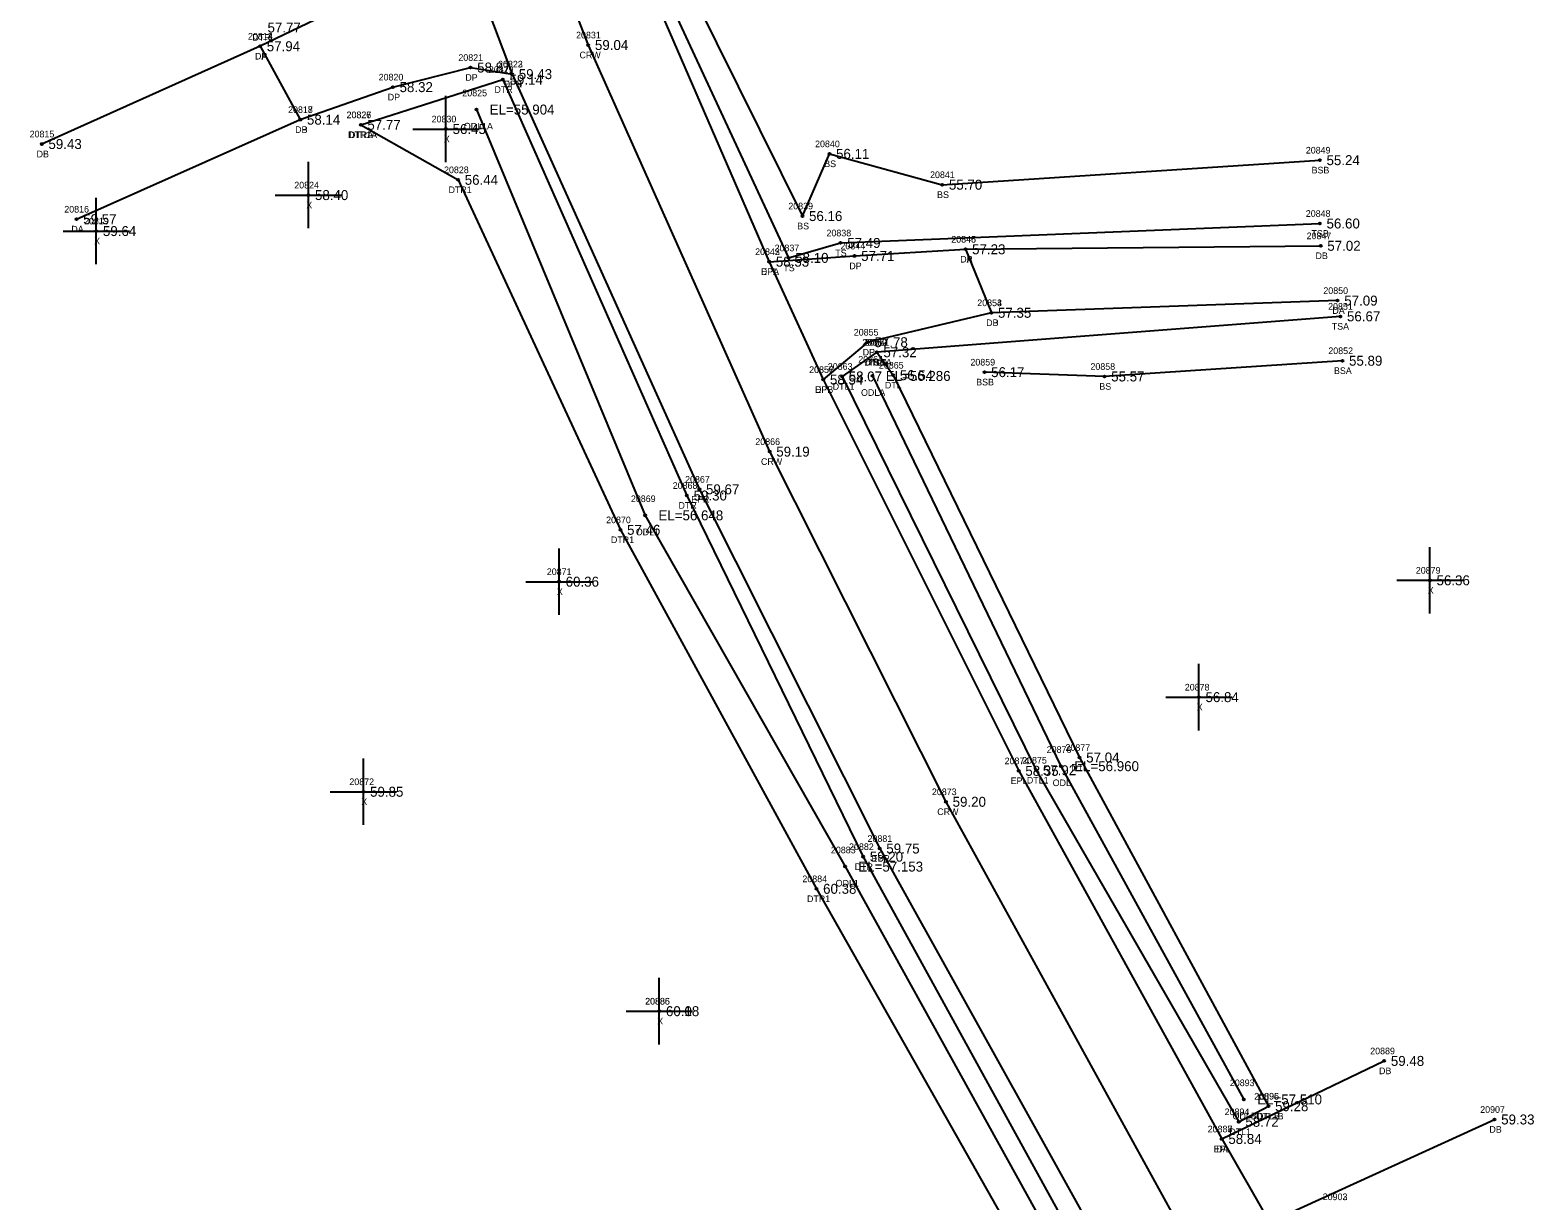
# Model space of a CAD drawing. Extents: x 2396547 to 2397655, y 770185 to 772649.
# Drawn here: x 2397059 to 2397285.6, y 770939.8 to 771116.1 of the extents above; entities that cross this region are included whole.
import ezdxf

# ---------------------------------------------------------------- set-up
doc = ezdxf.new("R2010")
doc.units = 0
for name, color, linetype in [('RD_DTM_BkLn1', 7, 'Continuous'), ('RD_DTM_BkLn2', 7, 'Continuous'), ('RD_DTM_BkLn_txCode', 7, 'Continuous'), ('RD_EX_Driveway', 7, 'Continuous'), ('RD_EX_Driveway_txCode', 7, 'Continuous'), ('RD_EX_H2O', 7, 'Continuous'), ('RD_EX_H2O_txCode', 7, 'Continuous'), ('RD_EX_Misc', 7, 'Continuous'), ('RD_EX_Misc_txCode', 7, 'Continuous'), ('RD_EX_Road', 7, 'Continuous'), ('RD_EX_Road_txCode', 7, 'Continuous'), ('RD_EX_TX_Driveway_ELEV', 7, 'Continuous'), ('RD_EX_TX_H2O_ELEV', 7, 'Continuous'), ('RD_EX_TX_Misc_ELEV', 7, 'Continuous'), ('RD_EX_TX_Road_ELEV', 7, 'Continuous'), ('RD_HC_Survey_ELEV', 7, 'Continuous'), ('RD_HC_Survey_txCode', 7, 'Continuous'), ('RD_SMD_Locator', 7, 'Continuous')]:
    doc.layers.add(name, color=color, linetype=linetype)

msp = doc.modelspace()

# ---------------------------------------------------------------- linework, layer by layer
at = {"layer": 'RD_DTM_BkLn1'}
msp.add_lwpolyline([(2397104.78, 771217.07), (2397119.02, 771175.87), (2397143.13, 771113.88), (2397170.45, 771052.64), (2397197.01, 770999.9), (2397235.12, 770930.63), (2397270.14, 770871.5)], dxfattribs=at)
at = {"layer": 'RD_DTM_BkLn2'}
msp.add_line((2397256.41, 771073.01), (2397186.58, 771067.61), dxfattribs=at)
for points in [[(2397076.78, 771367.04), (2397097.18, 771355.59), (2397095.19, 771340.51), (2397107.46, 771294.95), (2397125.86, 771232.19), (2397125.86, 771232.19), (2397138.17, 771181.02), (2397159.24, 771120.76), (2397175.38, 771088.12), (2397179.45, 771097.49), (2397196.45, 771092.84), (2397253.33, 771096.54)], [(2397076.87, 771363.73), (2397092.63, 771353.52), (2397090.96, 771344.27), (2397084.99, 771338.48), (2397096.6, 771290.87), (2397116.69, 771229.78), (2397116.69, 771229.78), (2397133.23, 771179.22), (2397155.87, 771119.34), (2397173.3, 771081.82), (2397181.13, 771084.07), (2397253.33, 771087)], [(2397256.72, 771066.33), (2397220.89, 771063.96), (2397202.81, 771064.61)]]:
    msp.add_lwpolyline(points, dxfattribs=at)
at = {"layer": 'RD_EX_Driveway'}
for p, q in [((2397093.7, 771113.7), (2397060.81, 771098.97)), ((2397066.05, 771087.65), (2397099.75, 771102.64)), ((2397199.94, 771083.12), (2397253.45, 771083.64)), ((2397256, 771075.39), (2397203.84, 771073.55)), ((2397238.54, 770949.11), (2397263.02, 770960.87)), ((2397245.72, 770936.59), (2397279.64, 770952.05))]:
    msp.add_line(p, q, dxfattribs=at)
for points in [[(2397122.66, 771133.29), (2397116.06, 771126.12), (2397107.96, 771120.55), (2397093.7, 771113.7), (2397099.75, 771102.64), (2397113.7, 771107.54), (2397125.39, 771110.49), (2397131.66, 771109.5)], [(2397170.38, 771081.25), (2397183.23, 771082.11), (2397199.94, 771083.12), (2397203.84, 771073.55), (2397185.24, 771069.12), (2397178.53, 771063.49)]]:
    msp.add_lwpolyline(points, dxfattribs=at)
at = {"layer": 'RD_EX_H2O'}
for points in [[(2397108.85, 771101.86), (2397130.27, 771108.67), (2397157.99, 771046.03), (2397184.53, 770991.63), (2397224.53, 770918.86), (2397257.48, 770863.23)], [(2397126.28, 771104.16), (2397151.7, 771043.04), (2397181.8, 770990.14), (2397222.13, 770917.32), (2397255.11, 770861.71)], [(2397108.85, 771101.86), (2397123.52, 771093.58), (2397147.97, 771040.86), (2397177.5, 770986.79), (2397217.86, 770915.5), (2397251.15, 770859.33)], [(2397186.58, 771067.61), (2397181.36, 771063.96), (2397210.6, 771004.65), (2397241.1, 770951.7), (2397245.58, 770954.05)], [(2397186.58, 771067.61), (2397189.06, 771064.15), (2397217.13, 771006.57), (2397245.58, 770954.05)], [(2397185.94, 771064.04), (2397214.32, 771005.26), (2397241.89, 770955.07)]]:
    msp.add_lwpolyline(points, dxfattribs=at)
at = {"layer": 'RD_EX_Misc'}
for p, q in [((2397121.69, 771096.23), (2397121.69, 771106.23)), ((2397116.69, 771101.23), (2397126.69, 771101.23)), ((2397100.96, 771086.28), (2397100.96, 771096.28)), ((2397069.02, 771080.86), (2397069.02, 771090.86)), ((2397095.96, 771091.28), (2397105.96, 771091.28)), ((2397064.02, 771085.86), (2397074.02, 771085.86)), ((2397138.72, 771028.05), (2397138.72, 771038.05)), ((2397269.9, 771028.26), (2397269.9, 771038.26)), ((2397264.9, 771033.26), (2397274.9, 771033.26)), ((2397133.72, 771033.05), (2397143.72, 771033.05)), ((2397235.1, 771010.66), (2397235.1, 771020.66)), ((2397230.1, 771015.66), (2397240.1, 771015.66)), ((2397109.26, 770996.41), (2397109.26, 771006.41)), ((2397104.26, 771001.41), (2397114.26, 771001.41)), ((2397153.83, 770963.36), (2397153.83, 770973.36)), ((2397153.83, 770963.36), (2397153.83, 770973.36)), ((2397148.83, 770968.36), (2397158.83, 770968.36)), ((2397148.83, 770968.36), (2397158.83, 770968.36))]:
    msp.add_line(p, q, dxfattribs=at)
at = {"layer": 'RD_EX_Road'}
for points in [[(2397113.76, 771228.75), (2397130.87, 771177.98), (2397154.19, 771118.49), (2397170.38, 771081.25), (2397178.53, 771063.49), (2397207.96, 771004.56), (2397238.54, 770949.11), (2397245.72, 770936.59), (2397280.76, 770876.73)], [(2397093.16, 771212.62), (2397108.35, 771171.65), (2397122.66, 771133.29), (2397131.66, 771109.5), (2397159.86, 771046.96), (2397187.02, 770992.86), (2397227.29, 770920.43), (2397260.16, 770864.73)]]:
    msp.add_lwpolyline(points, dxfattribs=at)
at = {"layer": 'RD_SMD_Locator'}
for centre in [(2397093.7, 771113.7), (2397093.7, 771113.7), (2397143.13, 771113.88), (2397125.39, 771110.49), (2397130.27, 771108.67), (2397131.66, 771109.5), (2397131.66, 771109.5), (2397113.7, 771107.54), (2397126.28, 771104.16), (2397099.75, 771102.64), (2397099.75, 771102.64), (2397108.85, 771101.86), (2397108.85, 771101.86), (2397121.69, 771101.23), (2397060.81, 771098.97), (2397179.45, 771097.49), (2397253.33, 771096.54), (2397123.52, 771093.58), (2397196.45, 771092.84), (2397100.96, 771091.28), (2397066.05, 771087.65), (2397175.38, 771088.12), (2397069.02, 771085.86), (2397253.33, 771087), (2397181.13, 771084.07), (2397199.94, 771083.12), (2397199.94, 771083.12), (2397253.45, 771083.64), (2397170.38, 771081.25), (2397170.38, 771081.25), (2397173.3, 771081.82), (2397183.23, 771082.11), (2397256, 771075.39), (2397203.84, 771073.55), (2397203.84, 771073.55), (2397256.41, 771073.01), (2397185.24, 771069.12), (2397186.58, 771067.61), (2397186.58, 771067.61), (2397186.58, 771067.61), (2397256.72, 771066.33), (2397178.53, 771063.49), (2397178.53, 771063.49), (2397181.36, 771063.96), (2397185.94, 771064.04), (2397189.06, 771064.15), (2397202.81, 771064.61), (2397220.89, 771063.96), (2397170.45, 771052.64), (2397159.86, 771046.96), (2397157.99, 771046.03), (2397151.7, 771043.04), (2397147.97, 771040.86), (2397269.9, 771033.26), (2397138.72, 771033.05), (2397235.1, 771015.66), (2397217.13, 771006.57), (2397207.96, 771004.56), (2397210.6, 771004.65), (2397214.32, 771005.26), (2397109.26, 771001.41), (2397197.01, 770999.9), (2397187.02, 770992.86), (2397181.8, 770990.14), (2397184.53, 770991.63), (2397177.5, 770986.79), (2397153.83, 770968.36), (2397153.83, 770968.36), (2397263.02, 770960.87), (2397241.89, 770955.07), (2397245.58, 770954.05), (2397245.58, 770954.05), (2397241.1, 770951.7), (2397279.64, 770952.05), (2397238.54, 770949.11), (2397238.54, 770949.11)]:
    msp.add_circle(centre, 0.15, dxfattribs=at)

# ---------------------------------------------------------------- texts
at = {"layer": 'RD_DTM_BkLn_txCode'}
for s, p in [('20840', (2397177.29, 771098.49)), ('20849', (2397251.21, 771097.54)), ('BS', (2397178.67, 771095.49)), ('20841', (2397194.61, 771093.84)), ('BSB', (2397252.08, 771094.54)), ('20839', (2397173.26, 771089.12)), ('BS', (2397195.67, 771090.84)), ('20848', (2397251.21, 771088)), ('BS', (2397174.6, 771086.12)), ('20838', (2397179.01, 771085.07)), ('TSB', (2397252.06, 771085)), ('20837', (2397171.19, 771082.82)), ('TS', (2397180.33, 771082.07)), ('TS', (2397172.51, 771079.82)), ('20851', (2397254.57, 771074.01)), ('TSA', (2397255.12, 771071.01)), ('20860', (2397184.4, 771068.61)), ('20852', (2397254.6, 771067.33)), ('TSB', (2397185.32, 771065.61)), ('20859', (2397200.69, 771065.61)), ('20858', (2397218.77, 771064.96)), ('BSA', (2397255.45, 771064.33)), ('BSB', (2397201.56, 771062.61)), ('BS', (2397220.11, 771061.96))]:
    msp.add_text(s, height=1, dxfattribs=at).set_placement(p)
at = {"layer": 'RD_EX_Driveway_txCode'}
for s, p in [('20813', (2397091.87, 771114.7)), ('20814', (2397091.87, 771114.7)), ('DA', (2397092.91, 771111.7)), ('DP', (2397092.92, 771111.7)), ('20821', (2397123.56, 771111.49)), ('20822', (2397129.54, 771110.5)), ('20820', (2397111.55, 771108.54)), ('DP', (2397124.61, 771108.49)), ('DPB', (2397130.4, 771107.5)), ('DP', (2397112.92, 771105.54)), ('20817', (2397097.91, 771103.64)), ('20818', (2397097.91, 771103.64)), ('DB', (2397098.97, 771100.64)), ('DP', (2397098.97, 771100.64)), ('20815', (2397058.98, 771099.97)), ('DB', (2397060.03, 771096.97)), ('20816', (2397064.2, 771088.65)), ('DA', (2397065.26, 771085.65)), ('20847', (2397251.33, 771084.64)), ('20843', (2397168.26, 771082.25)), ('20844', (2397181.11, 771083.11)), ('20846', (2397197.8, 771084.12)), ('20845', (2397197.82, 771084.12)), ('DP', (2397182.45, 771080.11)), ('DA', (2397199.15, 771081.12)), ('DP', (2397199.16, 771081.12)), ('DB', (2397252.67, 771081.64)), ('DPA', (2397169.12, 771079.25)), ('20850', (2397253.85, 771076.39)), ('20853', (2397201.72, 771074.55)), ('20854', (2397201.72, 771074.55)), ('DA', (2397255.21, 771073.39)), ('DB', (2397203.06, 771071.55)), ('DP', (2397203.06, 771071.55)), ('20855', (2397183.12, 771070.12)), ('DP', (2397184.46, 771067.12)), ('20856', (2397176.39, 771064.49)), ('DPB', (2397177.28, 771061.49)), ('20889', (2397260.91, 770961.87)), ('DB', (2397262.24, 770958.87)), ('20907', (2397277.48, 770953.05)), ('20888', (2397236.43, 770950.11)), ('DB', (2397278.86, 770950.05)), ('DA', (2397237.75, 770947.11))]:
    msp.add_text(s, height=1, dxfattribs=at).set_placement(p)
at = {"layer": 'RD_EX_H2O_txCode'}
for s, p in [('DTR', (2397092.54, 771114.52)), ('20829', (2397128.15, 771109.67)), ('20825', (2397124.16, 771106.16)), ('DTR', (2397129, 771106.67)), ('20826', (2397106.71, 771102.86)), ('20827', (2397106.73, 771102.86)), ('ODL1A', (2397124.38, 771101.16)), ('DTR1A', (2397106.93, 771099.86)), ('DTRA', (2397107.09, 771099.86)), ('20828', (2397121.4, 771094.58)), ('DTR1', (2397122.08, 771091.58)), ('20862', (2397184.44, 771068.61)), ('20861', (2397184.73, 771068.61)), ('20863', (2397179.21, 771064.96)), ('20864', (2397183.8, 771066.04)), ('DTL1A', (2397184.69, 771065.61)), ('DTLA', (2397184.85, 771065.61)), ('20865', (2397186.91, 771065.15)), ('DTL1', (2397179.95, 771061.96)), ('DTL', (2397187.81, 771062.15)), ('ODLA', (2397184.21, 771061.04)), ('20868', (2397155.85, 771047.03)), ('20869', (2397149.55, 771045.04)), ('DTR', (2397156.72, 771044.03)), ('20870', (2397145.82, 771041.86)), ('ODL1', (2397150.29, 771040.04)), ('DTR1', (2397146.54, 771038.86)), ('20877', (2397215.01, 771007.57)), ('20875', (2397208.48, 771005.65)), ('20876', (2397212.18, 771007.26)), ('DTL', (2397215.88, 771004.57)), ('DTL1', (2397209.19, 771002.65)), ('ODL', (2397213.08, 771002.26)), ('20883', (2397179.68, 770992.14)), ('20882', (2397182.41, 770992.63)), ('DTR', (2397183.26, 770989.63)), ('20884', (2397175.38, 770987.79)), ('ODL1', (2397180.39, 770987.14)), ('DTR1', (2397176.07, 770984.79)), ('20893', (2397239.77, 770957.07)), ('20896', (2397243.44, 770955.05)), ('20895', (2397243.46, 770955.05)), ('20894', (2397238.98, 770952.7)), ('ODLB', (2397240.17, 770952.07)), ('DTL1B', (2397243.7, 770952.05)), ('DTLB', (2397243.86, 770952.05)), ('DTL1', (2397239.69, 770949.7)), ('20902', (2397253.76, 770939.9)), ('20903', (2397253.76, 770939.9))]:
    msp.add_text(s, height=1, dxfattribs=at).set_placement(p)
at = {"layer": 'RD_EX_Misc_txCode'}
for s, p in [('20830', (2397119.53, 771102.23)), ('X', (2397121.37, 771099.23)), ('20824', (2397098.84, 771092.28)), ('X', (2397100.65, 771089.28)), ('20819', (2397067.18, 771086.86)), ('X', (2397068.7, 771083.86)), ('20871', (2397136.88, 771034.05)), ('20879', (2397267.78, 771034.26)), ('X', (2397138.4, 771031.05)), ('X', (2397269.58, 771031.26)), ('20878', (2397232.98, 771016.66)), ('X', (2397234.78, 771013.66)), ('20872', (2397107.14, 771002.41)), ('X', (2397108.94, 770999.41)), ('20886', (2397151.68, 770969.36)), ('20885', (2397151.71, 770969.36)), ('X', (2397153.51, 770966.36)), ('X', (2397153.51, 770966.36))]:
    msp.add_text(s, height=1, dxfattribs=at).set_placement(p)
at = {"layer": 'RD_EX_Road_txCode'}
for s, p in [('20823', (2397129.54, 771110.5)), ('EPR', (2397130.43, 771107.5)), ('20842', (2397168.26, 771082.25)), ('EPL', (2397169.18, 771079.25)), ('20857', (2397176.41, 771064.49)), ('EPL', (2397177.32, 771061.49)), ('20867', (2397157.71, 771047.96)), ('EPR', (2397158.63, 771044.96)), ('20874', (2397205.84, 771005.56)), ('EPL', (2397206.75, 771002.56)), ('20881', (2397185.19, 770993.86)), ('EPR', (2397185.8, 770990.86)), ('20887', (2397236.43, 770950.11)), ('EPL', (2397237.34, 770947.11))]:
    msp.add_text(s, height=1, dxfattribs=at).set_placement(p)
at = {"layer": 'RD_EX_TX_Driveway_ELEV'}
for s, p in [('57.94', (2397094.7, 771112.95)), ('57.94', (2397094.7, 771112.95)), ('58.87', (2397126.39, 771109.74)), ('59.43', (2397132.66, 771108.75)), ('58.32', (2397114.7, 771106.79)), ('58.14', (2397100.75, 771101.89)), ('58.14', (2397100.75, 771101.89)), ('59.43', (2397061.81, 771098.22)), ('59.57', (2397067.05, 771086.9)), ('57.23', (2397200.94, 771082.37)), ('57.23', (2397200.94, 771082.37)), ('57.02', (2397254.45, 771082.89)), ('58.53', (2397171.38, 771080.5)), ('57.71', (2397184.23, 771081.36)), ('57.35', (2397204.84, 771072.8)), ('57.35', (2397204.84, 771072.8)), ('57.09', (2397257, 771074.64)), ('57.78', (2397186.24, 771068.37)), ('58.54', (2397179.53, 771062.74)), ('59.48', (2397264.02, 770960.12)), ('59.33', (2397280.64, 770951.3)), ('58.84', (2397239.54, 770948.36))]:
    msp.add_text(s, height=1.5, dxfattribs=at).set_placement(p)
at = {"layer": 'RD_EX_TX_H2O_ELEV'}
for s, p in [('57.77', (2397094.81, 771115.77)), ('59.14', (2397131.27, 771107.92)), ('EL=55.904', (2397128.28, 771103.41)), ('57.77', (2397109.85, 771101.11)), ('57.77', (2397109.85, 771101.11)), ('56.44', (2397124.52, 771092.83)), ('57.32', (2397187.58, 771066.86)), ('57.32', (2397187.58, 771066.86)), ('56.54', (2397190.06, 771063.4)), ('58.07', (2397182.36, 771063.21)), ('EL=56.286', (2397187.94, 771063.29)), ('59.30', (2397158.99, 771045.28)), ('EL=56.648', (2397153.7, 771042.29)), ('57.46', (2397148.97, 771040.11)), ('EL=56.960', (2397216.32, 771004.51)), ('57.04', (2397218.13, 771005.82)), ('57.92', (2397211.6, 771003.9)), ('EL=57.153', (2397183.8, 770989.39)), ('59.20', (2397185.53, 770990.88)), ('60.38', (2397178.5, 770986.04)), ('EL=57.510', (2397243.89, 770954.32)), ('59.28', (2397246.58, 770953.3)), ('59.28', (2397246.58, 770953.3)), ('58.72', (2397242.1, 770950.95))]:
    msp.add_text(s, height=1.5, dxfattribs=at).set_placement(p)
at = {"layer": 'RD_EX_TX_Misc_ELEV'}
for s, p in [('56.45', (2397122.69, 771100.48)), ('56.11', (2397180.45, 771096.74)), ('55.24', (2397254.33, 771095.79)), ('55.70', (2397197.45, 771092.09)), ('58.40', (2397101.96, 771090.53)), ('56.16', (2397176.38, 771087.37)), ('56.60', (2397254.33, 771086.25)), ('59.64', (2397070.02, 771085.11)), ('57.49', (2397182.13, 771083.32)), ('58.10', (2397174.3, 771081.07)), ('56.67', (2397257.41, 771072.26)), ('57.32', (2397187.58, 771066.86)), ('56.17', (2397203.81, 771063.86)), ('55.89', (2397257.72, 771065.58)), ('55.57', (2397221.89, 771063.21)), ('60.36', (2397139.72, 771032.3)), ('56.36', (2397270.9, 771032.51)), ('56.84', (2397236.1, 771014.91)), ('59.85', (2397110.26, 771000.66)), ('60.08', (2397154.83, 770967.61)), ('60.18', (2397154.83, 770967.61))]:
    msp.add_text(s, height=1.5, dxfattribs=at).set_placement(p)
at = {"layer": 'RD_EX_TX_Road_ELEV'}
for s, p in [('59.43', (2397132.66, 771108.75)), ('58.53', (2397171.38, 771080.5)), ('58.54', (2397179.53, 771062.74)), ('59.67', (2397160.86, 771046.21)), ('58.35', (2397208.96, 771003.81)), ('59.75', (2397188.02, 770992.11)), ('58.84', (2397239.54, 770948.36))]:
    msp.add_text(s, height=1.5, dxfattribs=at).set_placement(p)
at = {"layer": 'RD_HC_Survey_ELEV'}
for s, p in [('59.04', (2397144.13, 771113.13)), ('59.19', (2397171.45, 771051.89)), ('59.20', (2397198.01, 770999.15))]:
    msp.add_text(s, height=1.5, dxfattribs=at).set_placement(p)
at = {"layer": 'RD_HC_Survey_txCode'}
for s, p in [('20831', (2397141.29, 771114.88)), ('CRW', (2397141.81, 771111.88)), ('20866', (2397168.29, 771053.64)), ('CRW', (2397169.14, 771050.64)), ('20873', (2397194.89, 771000.9)), ('CRW', (2397195.69, 770997.9))]:
    msp.add_text(s, height=1, dxfattribs=at).set_placement(p)

doc.saveas('drawing.dxf')
